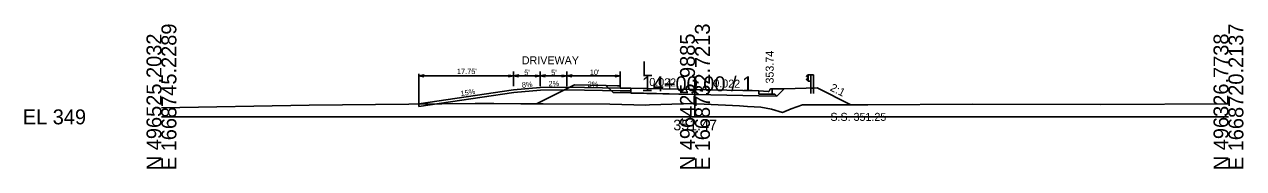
# Model space of a CAD drawing. Extents: x -26 to 203, y -10 to 5517.
# Drawn here: x -25.7 to 202.8, y 3990.3 to 4017.3 of the extents above; entities that cross this region are included whole.
import ezdxf

# ---------------------------------------------------------------- set-up
doc = ezdxf.new("R2010")
doc.units = 0
for name, color, linetype in [('Exist Cross Section Cell', 7, 'Continuous'), ('Exist XS Center Line Elevation Label', 7, 'Continuous'), ('Exist XS Ground Line', 7, 'Continuous'), ('Prop XS Earthwork Shape', 7, 'Continuous'), ('Prop XS Finish Grade', 7, 'Continuous'), ('Prop XS Finish Grade Concrete', 7, 'Continuous'), ('Prop XS Finish Grade CurbGutter', 7, 'Continuous'), ('Prop XS Finish Grade Earthwork', 7, 'Continuous'), ('Prop XS Finish Grade Pavement', 7, 'Continuous'), ('Prop XS Geopak Shape', 7, 'Continuous'), ('Prop XS Hydro Elevations', 7, 'Continuous'), ('Prop XS Pvmt Edge Slope', 7, 'Continuous'), ('Prop XS SE Text', 7, 'Continuous'), ('Prop XS Side Slope Text', 7, 'Continuous'), ('Prop XS SS Elevation Text', 7, 'Continuous'), ('Prop XS Subgrade CurbGutter', 7, 'Continuous'), ('Prop XS Subgrade Earthwork', 7, 'Continuous'), ('Prop XSC Text', 7, 'Continuous'), ('Typical Guardrail CELL', 7, 'Continuous'), ('Typical Terminator CELL', 7, 'Continuous')]:
    doc.layers.add(name, color=color, linetype=linetype)

msp = doc.modelspace()

# ---------------------------------------------------------------- linework, layer by layer
at = {"layer": 'Exist Cross Section Cell'}
for p, q in [((100, 4000), (100, 4007.59)), ((0, 4000), (100, 4000)), ((100, 4000), (200, 4000))]:
    msp.add_line(p, q, dxfattribs=at)
at = {"layer": 'Exist XS Ground Line'}
for p, q in [((0, 4001.72), (27.69, 4002.21)), ((27.69, 4002.21), (58.82, 4002.52)), ((58.82, 4002.52), (62.29, 4002.53)), ((62.29, 4002.53), (67.38, 4002.44)), ((67.38, 4002.44), (71.53, 4002.44)), ((71.53, 4002.44), (84.02, 4002.37)), ((84.02, 4002.37), (90.8, 4002.22)), ((90.8, 4002.22), (91.46, 4002.26)), ((91.46, 4002.26), (97.77, 4002.42)), ((97.77, 4002.42), (99.7, 4002.48)), ((99.7, 4002.48), (100, 4002.47)), ((100, 4002.47), (101.7, 4002.38)), ((101.7, 4002.38), (108.34, 4002.09)), ((108.34, 4002.09), (109.83, 4001.97)), ((109.83, 4001.97), (112.33, 4001.84)), ((112.33, 4001.84), (114.35, 4001.41)), ((118.03, 4001.51), (120.14, 4002.24)), ((120.14, 4002.24), (132.38, 4002.26)), ((132.38, 4002.26), (151.94, 4002.38)), ((151.94, 4002.38), (176.09, 4002.34)), ((176.09, 4002.34), (200, 4002.46)), ((114.35, 4001.41), (116.38, 4000.82)), ((116.38, 4000.82), (118.03, 4001.51))]:
    msp.add_line(p, q, dxfattribs=at)
at = {"layer": 'Prop XS Earthwork Shape'}
msp.add_lwpolyline([(70.31, 4002.44), (71.53, 4002.44), (84.02, 4002.37), (90.8, 4002.22), (91.46, 4002.26), (97.77, 4002.42), (99.7, 4002.48), (100, 4002.47), (101.7, 4002.38), (108.34, 4002.09), (109.83, 4001.97), (112.33, 4001.84), (114.35, 4001.41), (116.38, 4000.82), (118.03, 4001.51), (120.14, 4002.24), (129.23, 4002.25), (122.91, 4005.41), (116.74, 4005.28), (115.33, 4003.87), (112, 4003.94), (100, 4004.2), (88, 4004.47), (84.67, 4004.54), (83.32, 4005.89), (77.45, 4006.01)], close=True, dxfattribs=at)
at = {"layer": 'Prop XS Finish Grade'}
msp.add_line((114.5, 4005.24), (116.74, 4005.28), dxfattribs=at)
at = {"layer": 'Prop XS Finish Grade Concrete'}
for p, q in [((66, 4005.08), (48.25, 4002.42)), ((71, 4005.48), (66, 4005.08)), ((76, 4005.58), (71, 4005.48)), ((86, 4005.38), (76, 4005.58)), ((88, 4005.38), (86, 4005.38))]:
    msp.add_line(p, q, dxfattribs=at)
at = {"layer": 'Prop XS Finish Grade CurbGutter'}
for p, q in [((112, 4004.86), (113.75, 4004.75)), ((113.75, 4004.75), (113.87, 4004.78)), ((113.87, 4004.78), (113.97, 4004.87)), ((113.97, 4004.87), (114.03, 4005.12)), ((114.03, 4005.12), (114.12, 4005.21)), ((114.25, 4005.24), (114.12, 4005.21)), ((114.5, 4005.24), (114.25, 4005.24))]:
    msp.add_line(p, q, dxfattribs=at)
at = {"layer": 'Prop XS Finish Grade Earthwork'}
for p, q in [((116.74, 4005.28), (122.91, 4005.41)), ((122.91, 4005.41), (129.23, 4002.25))]:
    msp.add_line(p, q, dxfattribs=at)
at = {"layer": 'Prop XS Finish Grade Pavement'}
for p, q in [((88, 4005.38), (100, 4005.12)), ((100, 4005.12), (112, 4004.86))]:
    msp.add_line(p, q, dxfattribs=at)
at = {"layer": 'Prop XS Geopak Shape'}
msp.add_lwpolyline([(86.13, 4005.37), (86.03, 4005.46), (85.97, 4005.71), (85.88, 4005.8), (85.75, 4005.84), (85.5, 4005.84), (83.32, 4005.89), (77.45, 4006.01), (70.31, 4002.44), (71.53, 4002.44), (84.02, 4002.37), (90.8, 4002.22), (91.46, 4002.26), (97.77, 4002.42), (99.7, 4002.48), (100, 4002.47), (101.7, 4002.38), (108.34, 4002.09), (109.83, 4001.97), (112.33, 4001.84), (114.35, 4001.41), (116.38, 4000.82), (118.03, 4001.51), (120.14, 4002.24), (129.23, 4002.25), (122.91, 4005.41), (116.74, 4005.28), (114.5, 4005.24), (114.25, 4005.24), (114.12, 4005.21), (114.03, 4005.12), (113.97, 4004.87), (113.87, 4004.78), (113.75, 4004.75), (112, 4004.86), (100, 4005.12), (88, 4005.38), (86.25, 4005.35)], close=True, dxfattribs=at)
at = {"layer": 'Prop XS Pvmt Edge Slope'}
for p, q in [((114.5, 4004.23), (115, 4004.22)), ((115, 4004.22), (115.33, 4003.87))]:
    msp.add_line(p, q, dxfattribs=at)
at = {"layer": 'Prop XS Subgrade CurbGutter'}
for p, q in [((88, 4005.38), (88, 4004.8)), ((112, 4004.86), (112, 4004.28)), ((112, 4004.28), (114.5, 4004.23)), ((114.5, 4004.23), (114.5, 4005.24))]:
    msp.add_line(p, q, dxfattribs=at)
at = {"layer": 'Prop XS Subgrade Earthwork'}
for p, q in [((66.06, 4004.58), (48.25, 4001.91)), ((71.02, 4004.98), (66.06, 4004.58)), ((76.01, 4005.08), (71.02, 4004.98)), ((85.99, 4004.88), (75.99, 4005.08)), ((88, 4004.88), (86, 4004.88)), ((88, 4004.88), (88, 4004.46)), ((88, 4004.46), (88, 4004.47)), ((100, 4004.2), (88, 4004.46)), ((112, 4003.94), (100, 4004.2)), ((112, 4003.94), (112, 4003.95)), ((112, 4003.95), (115.33, 4003.87)), ((115.33, 4003.87), (116.74, 4005.28)), ((48.25, 4002.42), (48.25, 4001.91))]:
    msp.add_line(p, q, dxfattribs=at)
at = {"layer": 'Prop XSC Text'}
for p, q in [((66, 4005.78), (66, 4008.5)), ((71, 4005.78), (71, 4008.5)), ((76, 4005.78), (76, 4008.5)), ((86, 4005.78), (86, 4008.5)), ((48.25, 4002.42), (48.25, 4008.07)), ((66, 4007.68), (48.25, 4007.68)), ((71, 4007.68), (66, 4007.68)), ((76, 4007.68), (71, 4007.68)), ((86, 4007.68), (76, 4007.68))]:
    msp.add_line(p, q, dxfattribs=at)
at = {"layer": 'Typical Guardrail CELL'}
for p, q in [((121.23, 4007.87), (120.94, 4007.67)), ((121.23, 4007.34), (120.94, 4007.54)), ((121.23, 4007.25), (120.94, 4007.05)), ((121.23, 4006.71), (120.94, 4006.92)), ((121.73, 4007.87), (121.23, 4007.87)), ((121.23, 4007.87), (121.23, 4006.71)), ((121.23, 4007.29), (121.23, 4007.34)), ((121.23, 4007.29), (121.23, 4007.25)), ((121.73, 4006.71), (121.23, 4006.71)), ((121.73, 4007.87), (121.73, 4005.39)), ((121.73, 4007.87), (122.23, 4007.87)), ((122.23, 4007.87), (122.23, 4005.39)), ((121.73, 4005.39), (122.23, 4005.39)), ((121.73, 4005.39), (121.73, 4004.38)), ((122.23, 4005.39), (122.23, 4004.38))]:
    msp.add_line(p, q, dxfattribs=at)
for centre, start, end in [((120.99, 4007.61), 125.003, 235.0112), ((120.99, 4006.98), 125.0059, 235.0366)]:
    msp.add_arc(centre, 0.0776, start, end, dxfattribs=at)
at = {"layer": 'Typical Terminator CELL'}
for points in [[(49.19, 4007.52), (48.25, 4007.68), (49.2, 4007.85), (49.08, 4007.68)], [(65.06, 4007.84), (66, 4007.68), (65.06, 4007.52), (65.18, 4007.68)], [(66.94, 4007.52), (66, 4007.68), (66.94, 4007.85), (66.82, 4007.68)], [(70.06, 4007.84), (71, 4007.68), (70.06, 4007.52), (70.18, 4007.68)], [(71.94, 4007.52), (71, 4007.68), (71.94, 4007.85), (71.82, 4007.68)], [(75.06, 4007.84), (76, 4007.68), (75.06, 4007.52), (75.18, 4007.68)], [(76.94, 4007.52), (76, 4007.68), (76.94, 4007.85), (76.82, 4007.68)], [(85.06, 4007.84), (86, 4007.68), (85.06, 4007.52), (85.18, 4007.68)]]:
    msp.add_lwpolyline(points, close=True, dxfattribs=at)

# ---------------------------------------------------------------- texts
at = {"layer": 'Exist Cross Section Cell'}
for s, p in [('N 496525.2032', (0, 3990)), ('E 1668745.2289', (2.8, 3990)), ('N 496425.9885', (100, 3990)), ('E 1668732.7213', (102.8, 3990)), ('N 496326.7738', (200, 3990)), ('E 1668720.2137', (202.8, 3990))]:
    msp.add_text(s, height=2.8, rotation=90, dxfattribs=at).set_placement(p)
for s, p in [('L', (90, 4007.59)), ('14+00.00 / 1', (90, 4004.79)), ('EL 349', (-26, 3998.6))]:
    msp.add_text(s, height=2.8, dxfattribs=at).set_placement(p)
at = {"layer": 'Exist XS Center Line Elevation Label'}
msp.add_text('351.47', height=2, dxfattribs=at).set_placement((95.94, 3997.47))
at = {"layer": 'Prop XS Hydro Elevations'}
msp.add_text('353.74', height=1.5, rotation=90, dxfattribs=at).set_placement((114.75, 4006.24))
at = {"layer": 'Prop XS SE Text'}
for p in [(91.43, 4005.8), (103.43, 4005.55)]:
    msp.add_text('0.022', height=1.5, rotation=358.7626, dxfattribs=at).set_placement(p)
at = {"layer": 'Prop XS Side Slope Text'}
msp.add_text('2:1', height=1.5, rotation=333.4349, dxfattribs=at).set_placement((125.19, 4004.99))
at = {"layer": 'Prop XS SS Elevation Text'}
msp.add_text('S.S. 351.25', height=1.5, dxfattribs=at).set_placement((125.38, 3999.25))
at = {"layer": 'Prop XSC Text'}
for s, height, p in [('DRIVEWAY', 1.5, (67.55, 4009.84)), ("17.75'", 1, (55.39, 4008.02)), ("5'", 1, (68.01, 4007.81)), ("5'", 1, (73.05, 4007.81)), ("10'", 1, (80.29, 4007.85))]:
    msp.add_text(s, height=height, dxfattribs=at).set_placement(p)
for s, rotation, p in [('8%', 4.5739, (67.59, 4005.45)), ('2%', 1.1458, (72.56, 4005.72)), ('2%', 358.8542, (79.88, 4005.62)), ('15%', 8.5308, (56.14, 4003.87))]:
    msp.add_text(s, height=1, rotation=rotation, dxfattribs=at).set_placement(p)

doc.saveas('drawing.dxf')
